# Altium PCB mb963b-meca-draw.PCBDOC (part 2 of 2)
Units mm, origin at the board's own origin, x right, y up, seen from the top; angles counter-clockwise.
Board outline 55.97 x 112.25 mm, 2 copper layers (Top, Bottom), stack 0.323 mm thick; 137 components, 131 nets, 523 pads, 261 vias.
Unrouted connection lines stored in the file: 17.
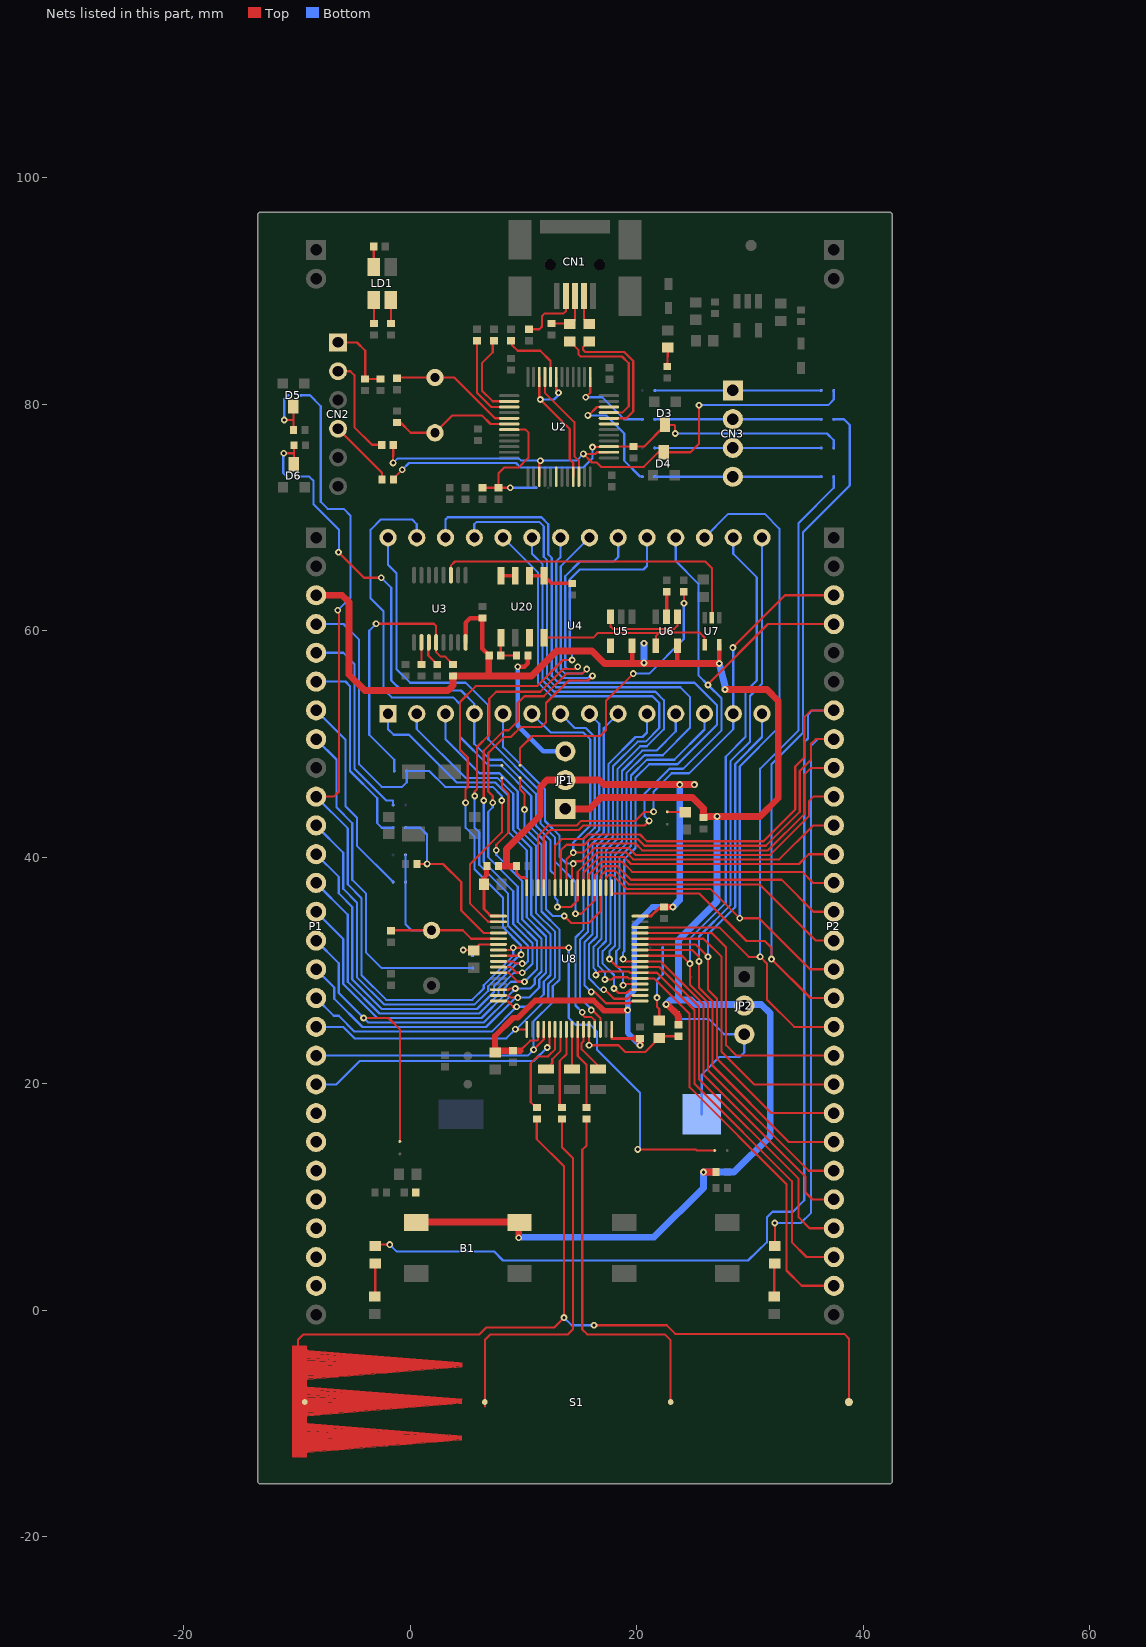
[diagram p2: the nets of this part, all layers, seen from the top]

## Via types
v1: diameter 0.6, hole 0.3, Top to Bottom, 261 vias

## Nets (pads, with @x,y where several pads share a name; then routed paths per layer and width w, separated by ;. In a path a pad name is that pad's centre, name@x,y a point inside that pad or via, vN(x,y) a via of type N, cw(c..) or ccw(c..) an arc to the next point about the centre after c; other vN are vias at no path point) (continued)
NETC25_1: C19.1 R29.2 U8.1 | length 5.4
  Top w0.254: C19.1@6.538,37.6 6.528,37.59 6.528,35.409 7.009,34.928 7.009,34.909 7.119,34.8 U8.1@7.8,34.8
  Top w0.4: C19.1@6.538,37.6 6.538,38.2 6.746,38.408 6.746,39.154 R29.2@6.792,39.2
NETCN1_1: CN2.1 R11.1 R101.2 | length 6.6
  Top w0.191: CN2.1@-6.362,85.439 -4.694,85.439 -3.965,84.71 R101.2@-3.965,82.211 -2.603,82.211 R11.1@-2.6,82.208
NETCN1_2: CN2.2 R13.1 | length 9.2
  Top w0.191: CN2.2@-6.362,82.899 -5.276,82.899 -4.921,82.544 -4.921,77.953 -3.366,76.398 -3.364,76.4 R13.1@-2.508,76.4
NETCN1_4: CN2.4 R14.1 | length 6.1
  Top w0.191: CN2.4@-6.362,77.819 -2.482,73.939 R14.1@-2.482,73.329
NETCN2_1: CN3.1 SB6.1 SB7.2 | length 14.7
  Bottom w0.191: SB6.1@21.6,81.2 CN3.1@28.5,81.2 SB7.2@36.3,81.2
NETCN2_2: CN3.2 SB8.1 SB9.2 | length 14.7
  Bottom w0.191: SB8.1@21.6,78.66 CN3.2@28.5,78.66 SB9.2@36.3,78.66
NETCN2_3: CN3.3 SB10.1 SB11.2 | length 14.7
  Bottom w0.191: SB10.1@21.6,76.12 CN3.3@28.5,76.12 SB11.2@36.3,76.12
NETCN2_4: CN3.4 SB12.1 SB13.2 | length 14.7
  Bottom w0.191: SB12.1@21.6,73.58 CN3.4@28.5,73.58 SB13.2@36.3,73.58
NETCN3_2: CN1.2 R10.1 | length 2.7
  Top w0.191: CN1.2@15.357,89.55 15.357,87.5 15.795,87.062 R10.1@15.8,87.062
NETCN3_3: CN1.3 R8.1 R9.1 | length 4.4
  Top w0.191: R8.1@12.5,87.108 14.085,87.108 R9.1@14.12,87.073 ; R9.1@14.1,87.062 R9.1@14.12,87.073 ; CN1.3@14.557,89.55 14.557,87.319 R9.1@14.12,87.073
NETCN3_4: CN1.4 R7.1 | length 5.8
  Top w0.191: R7.1@10.5,86.608 11.4,86.608 11.643,86.852 11.643,87.752 11.892,88 13.557,88 13.757,88.2 CN1.4@13.757,89.55
NETCR1_1: CR1.1 JP2.3 SB22.1 | length 16.6
  Bottom w0.191: SB22.1@23.7,26.3 23.7,25.7 24.129,25.7 26.4,25.7 27.74,24.36 JP2.3@29.5,24.36 29.5,22.75 29.1,22.35 27.3,22.35 25.75,20.8 CR1.1@25.75,17.3
NETJP1_3: JP1.3 R22.1 U5.4 U20.7 U20.8 | length 13.3
  Top w0.3: U20.8@8.012,64.84 U20.7@9.282,64.84
  Top w0.4: v1(9.5,56.8) 10.1,56.8 10.4,57.1 10.4,57.808 R22.1@10.408,57.8
  Bottom w0.4: v1(9.5,56.8) 9.5,51.6 11.76,49.34 JP1.3@13.7,49.34
NETLD1_2: LD1.2 R3.2 | length 2.1
  Top w0.191: R3.2@-1.7,87.108 LD1.2@-1.7,89.2
NETLD1_3: LD1.3 R2.2 | length 2.1
  Top w0.191: R2.2@-3.2,87.108 LD1.3@-3.2,89.2
NETLD1_4: LD1.4 R1.1 | length 1.8
  Top w0.191: R1.1@-3.208,93.9 -3.208,92.108 LD1.4@-3.2,92.1
NETLD2_1: LD2.1 R12.1 | length 1.7
  Top w0.191: R12.1@22.7,83.308 LD2.1@22.759,84.979
NETLD3_1: LD3.1 R39.1 | length 3
  Top w0.191: LD3.1@-3.139,1.203 -3.135,1.401 -3.08,1.456 R39.1@-3.08,4.138
NETLD4_1: LD4.1 R40.1 | length 3
  Top w0.191: LD4.1@32.141,1.203 32.141,4.079 R40.1@32.2,4.138
NETR1_1: R18.1 U6.2 | length 2.3
  Top w0.3: U6.2@22.645,61.213 22.659,61.199 R18.1@22.659,63.43
NETR2_2: R19.2 SB2.1 | length 25.7
  Top w0.191: SB2.1@9.7,48.1 9.7,49.6 10.8,50.7 16.8,50.7 17.3,51.2 17.3,53.8 v1(19.7,56.2) ; R19.2@24.159,63.43 24.178,63.411 v1(24.178,62.421)
  Bottom w0.191: v1(19.7,56.2) 21.111,56.2 24.163,59.252 24.163,62.421 v1(24.178,62.421)
NETR3_1: R21.1 R22.2 U20.1 | length 3
  Top w0.191: U20.1@8.012,59.379 8.008,59.375 R21.1@8.008,57.8 R22.2@9.392,57.8
NETR5_1: R20.1 SB1.1 U20.5 U20.6 | length 4
  Top w0.3: U20.6@10.552,64.84 U20.5@11.822,64.84
  Top w0.33: U20.5@11.822,64.84 12.49,64.172 14.312,64.172 R20.1@14.316,64.168
NETR6_2: R25.2 SB14.1 U3.12 | length 23.8
  Top w0.191: v1(-3,60.6) 2.1,60.6 2.3,60.4 U3.12@2.3,58.956 2.3,58.1 2.7,57.7 3.108,57.7 R25.2@3.8,57.008
  Bottom w0.191: v1(-3,60.6) -3.6,60 -3.6,50.8 -1.4,48.6 SB14.1@-1.4,47.6
NETR7_1: R23.1 U3.10 | length 1.9
  Top w0.191: R23.1@1,57.008 U3.10@1,58.956
NETR8_1: R24.1 U3.11 | length 2.3
  Top w0.191: U3.11@1.65,58.956 1.608,58.914 1.608,57.8 R24.1@2.4,57.008
NETR9_2: R6.2 U2.44 | length 5.8
  Top w0.191: R6.2@8.9,85.592 9.001,85.491 9.001,85.2 9.5,84.701 11.5,84.701 12.401,83.8 U2.44@12.401,82.389
NETR10_2: R5.2 U2.2 | length 7.7
  Top w0.191: R5.2@7.4,85.592 7.3,85.592 7.3,84.561 6.339,83.6 6.339,81.2 7.3,80.239 U2.2@8.751,80.239
NETR11_2: R4.2 U2.3 | length 8
  Top w0.191: R4.2@5.9,85.592 5.9,81 7.161,79.739 U2.3@8.751,79.739
NETR26_2: R28.2 SB16.1 U8.4 | length 15.9
  Top w0.191: R28.2@0.608,39.4 v1(1.5,39.4) 2.91,39.4 4.51,37.8 4.51,37.6 4.51,35.29 6.5,33.3 U8.4@7.8,33.3
  Bottom w0.191: SB16.1@-0.4,42.6 0.9,42.6 1.5,42 v1(1.5,39.4)
NETR30_1: R26.1 SB3.2 | length 1.6
  Top w0.191: SB3.2@22.7,44 24.3,44 R26.1@24.3,43.962
NETR34_2: R31.2 SB19.2 | length 6.7
  Top w0.191: v1(21.8,27.6) 21.8,26.8 22,26.6 R31.2@22,25.562
  Bottom w0.191: v1(21.8,27.6) 21.8,29.155 22.3,29.655 SB19.2@22.3,32
NETT1_3: U6.4 U7.4 U20.4 | length 16.4
  Top w0.191: U20.4@11.822,59.379 16.176,59.379 16.579,59.782 21.972,59.782 ; U6.4@21.695,58.673 21.695,59.505 21.972,59.782 ; U7.4@25.995,58.743 25.995,59.388 25.566,59.817 22.007,59.817 21.972,59.782
NETU1_3: U5.3 U6.1 | length 7.7
  Top w0.191: U5.3@17.695,61.213 17.691,61.209 17.691,60.363 17.904,60.15 23.327,60.15 23.595,60.418 U6.1@23.595,61.213
NETU3_2: U3.3 U7.2 | length 28.7
  Top w0.191: U3.3@3.6,64.9 3.6,65.738 3.962,66.1 3.975,66.113 26.041,66.113 26.645,65.509 26.645,64.5 U7.2@26.645,61.143
NRST: P1.10 SB5.1 SB100.2 U8.7 | length 109.5
  Top w0.191: P1.10@-8.3,45.34 -6.73,45.34 -6.275,45.795 -6.275,61.799 v1(-6.38,61.799) ; U8.7@7.8,31.8 8.9,31.8 v1(9.1,32) v1(14,32) ; v1(20.1,14.2) 25.21,14.2 25.31,14.1 SB5.1@26.9,14.1
  Bottom w0.191: SB100.2@-9.676,80.773 -8.839,80.773 -7.884,79.818 -7.884,71.365 -7.262,70.743 -5.863,70.743 -5.268,70.148 -5.268,62.911 v1(-6.38,61.799) ; P1.10@-8.3,45.34 -5.5,42.54 -5.5,37.6 -4.3,36.4 -4.3,29.6 -2.1,27.4 5.5,27.4 6.5,28.4 6.5,28.7 9.1,31.3 v1(9.1,32) ; v1(14,32) 14,25.8 14.6,25.2 15.9,25.2 16.5,24.6 16.5,23 20.3,19.2 20.3,14.4 v1(20.1,14.2)
OSC_IN: C8.2 U2.5 X1.2 | length 11.5
  Top w0.191: C8.2@-1.15,82.278 -1.15,82.34 X1.2@2.2,82.34 3.899,82.34 7.5,78.739 U2.5@8.751,78.739
OSC_OUT: C9.2 U2.6 X1.1 | length 11.2
  Top w0.191: C9.2@-1.15,78.362 -0.84,78.362 0.062,77.46 X1.1@2.2,77.46 3.74,79 6.339,79 7.1,78.239 U2.6@8.751,78.239
PA0: P1.15 SB1.2 SB4.1 U8.14 | length 61.2
  Top w0.191: v1(-4.1,25.8) -1.9,25.8 -0.9,24.8 SB4.1@-0.9,14.9 ; v1(7.6,40.6) 7.6,41.1 8.7,42.2 8.7,45.6 8.1,46.2 SB1.2@8.1,47 ; U8.14@7.8,28.3 8.684,28.3 8.784,28.4 v1(9.3,28.4)
  Bottom w0.191: P1.15@-8.3,32.64 -6.3,30.64 -6.3,28 v1(-4.1,25.8) -3.7,25.4 6.5,25.4 8.7,27.6 8.7,27.8 v1(9.3,28.4) 10.6,28.4 11,28.8 11,29.3 11.6,29.9 11.6,32.8 9.9,34.5 9.9,37.9 7.6,40.2 v1(7.6,40.6)
PA1: P1.16 U4.1 U8.15 | length 58.6
  Top w0.191: U8.15@7.8,27.8 8.7,27.8 8.9,27.6 v1(9.5,27.6)
  Bottom w0.191: P1.16@-8.3,30.1 -6.7,28.5 -6.7,27.5 -4.2,25 6.7,25 9.3,27.6 v1(9.5,27.6) 10.5,27.6 11.4,28.5 11.4,29.2 12,29.8 12,33 10.3,34.7 10.3,40.6 8.7,42.2 8.7,45.4 7.5,46.6 4.1,46.6 -0.1,50.8 -1.45,50.8 -1.95,51.3 U4.1@-1.95,52.66
PA2: P1.17 U4.2 U8.16 | length 56
  Top w0.191: U8.16@7.8,27.3 8.6,27.3 9.1,26.8 v1(9.4,26.8)
  Bottom w0.191: P1.17@-8.3,27.56 -6.74,26 -6.3,26 -4.9,24.6 7.2,24.6 v1(9.4,26.8) 10.7,26.8 11.8,27.9 11.8,29 12.4,29.6 12.4,33.2 10.7,34.9 10.7,40.8 9.1,42.4 9.1,45.6 7.7,47 4.89,47 0.59,51.3 U4.2@0.59,52.66
PA3: P1.18 U4.3 U8.17 | length 53.8
  Top w0.191: v1(9.3,24.8) U8.17@10.3,24.8
  Bottom w0.191: P1.18@-8.3,25.02 -5.9,25.02 -5.9,25 -4.9,24 8.5,24 v1(9.3,24.8) 9.381,24.8 12.2,27.619 12.2,28.8 12.8,29.4 12.8,33.4 11.1,35.1 11.1,41 9.5,42.6 9.5,45.8 7.9,47.4 6.13,47.4 3.13,50.4 U4.3@3.13,52.66
PA4: P1.19 SB2.2 U8.20 | length 48
  Top w0.191: SB2.2@9.7,47 9.7,46 10.1,45.6 v1(10.1,44.2) ; v1(10.9,23) 11.8,23.9 U8.20@11.8,24.8
  Bottom w0.191: P1.19@-8.3,22.48 10.38,22.48 v1(10.9,23) 10.9,25.5 12.6,27.2 12.6,28.6 13.2,29.2 13.2,33.6 11.6,35.2 11.6,41.1 10.1,42.6 v1(10.1,44.2)
PA5: P1.20 U8.21 | length 23.4
  Top w0.191: v1(12.1,23.2) 12.3,23.4 U8.21@12.3,24.8
  Bottom w0.191: P1.20@-8.3,19.94 -6.5,19.94 -4.44,22 10.9,22 v1(12.1,23.2)
PA6: R33.1 U8.22 | length 8.6
  Top w0.191: R33.1@11.185,17.908 11.178,17.915 11.097,17.915 10.657,18.355 10.657,21.796 11.261,22.4 12.17,22.4 12.221,22.451 12.221,22.465 12.8,23.044 U8.22@12.8,24.8
PA7: C27.2 U8.23 | length 4
  Top w0.191: C27.2@12,21.3 12.554,21.854 12.554,22.167 13.289,22.902 13.289,24.789 U8.23@13.3,24.8
PA8: P2.23 U4.16 U8.41 | length 70.5
  Top w0.191: U8.41@20.3,31.3 24,31.3 v1(24.7,30.6) 24.7,28.756 26.3,27.156 26.3,21.2 35.18,12.32 P2.23@37.42,12.32
  Bottom w0.191: v1(24.7,30.6) 24.7,32.8 27.866,35.966 27.866,48.866 29.6,50.6 29.6,54.6 30.6,55.6 30.6,64.7 28.53,66.77 U4.16@28.53,68.2
PA9: P2.22 U4.15 U8.42 | length 68.8
  Top w0.191: U8.42@20.3,31.8 24.9,31.8 25.5,31.2 v1(25.5,30.8) 25.5,28.483 26.7,27.283 26.7,21.6 33.44,14.86 P2.22@37.42,14.86
  Bottom w0.191: v1(25.5,30.8) 25.5,33 28.3,35.8 28.3,48.5 30,50.2 30,54.23 31.07,55.3 U4.15@31.07,68.2
PA10: P2.21 U4.14 U8.43 | length 51.5
  Top w0.191: U8.43@20.3,32.3 25.2,32.3 v1(26.3,31.2) 26.3,28.3 27.1,27.5 27.1,22.2 31.9,17.4 P2.21@37.42,17.4
  Bottom w0.191: v1(26.3,31.2) 26.3,33.2 28.7,35.6 28.7,48.23 31.07,50.6 U4.14@31.07,52.66
PA11: P2.20 U8.44 | length 27.4
  Top w0.191: U8.44@20.3,32.8 25.9,32.8 27.5,31.2 27.5,22.8 30.36,19.94 P2.20@37.42,19.94
PA12: P2.19 U8.45 | length 26.7
  Top w0.191: U8.45@20.3,33.3 26.625,33.3 27.9,32.025 27.9,23.4 28.82,22.48 P2.19@37.42,22.48
PA13: P2.18 SB13.1 U8.46 | length 67.7
  Top w0.191: U8.46@20.3,33.8 27.3,33.8 29.9,31.2 v1(30.9,31.2) 31.5,30.6 31.5,29.8 31.5,27.42 33.9,25.02 P2.18@37.42,25.02
  Bottom w0.191: v1(30.9,31.2) 30.9,47.8 34.3,51.2 34.3,69.5 37.4,72.6 SB13.1@37.4,73.58
PA14: P2.17 SB9.1 U8.49 | length 76.2
  Top w0.191: U8.49@17.8,37.3 17.8,36.8 25.5,36.8 29.7,32.6 31.3,32.6 31.9,32 v1(31.9,31) 35.34,27.56 P2.17@37.42,27.56
  Bottom w0.191: v1(31.9,31) 31.9,48.2 34.7,51 34.7,68.7 38.807,72.807 38.807,78.153 38.3,78.66 SB9.1@37.4,78.66
PA15: P2.16 U4.17 U8.50 | length 68.7
  Top w0.191: U8.50@17.3,37.3 17.3,38.2 17.5,38.4 17.9,38.4 19.1,37.2 26.5,37.2 v1(29.1,34.6) 30.8,34.6 35.3,30.1 P2.16@37.42,30.1
  Bottom w0.191: U4.17@25.99,68.2 28.09,70.3 31.3,70.3 32.6,69 32.6,51.5 29.1,48 29.1,34.8 29.3,34.6 v1(29.1,34.6)
PB0: R35.1 U8.26 | length 7.2
  Top w0.191: U8.26@14.8,24.8 14.8,22.438 15.569,21.669 R35.1@15.569,17.908
PB1: C29.2 U8.27 | length 4.2
  Top w0.191: U8.27@15.3,24.8 15.3,23.746 15.145,23.591 15.145,23.03 16.645,21.53 16.6,21.485 C29.2@16.6,21.3
PB2: P1.21 R31.1 R32.2 U8.28 | length 10.1
  Top w0.191: U8.28@15.8,24.8 v1(15.8,23.4) 18.4,23.4 19,22.8 20.762,22.8 R31.1@22,24.038 22.154,24.192 R32.2@23.7,24.192
PB3: P2.11 SB101.1 U4.4 U8.55 | length 82
  Top w0.191: v1(-6.316,66.92) -4.065,64.669 v1(-2.55,64.669) ; v1(13,35.6) 14.2,35.6 14.8,36.2 U8.55@14.8,37.3 14.8,38.7 16.5,40.4 19.1,40.4 19.7,39.8 32.6,39.8 35.6,42.8 P2.11@37.42,42.8
  Bottom w0.191: SB101.1@-9.795,73.594 -8.901,73.594 -8.522,73.215 -8.522,71.154 -6.271,68.903 -6.271,66.92 v1(-6.316,66.92) ; v1(-2.55,64.669) -1.658,63.777 -1.658,55.598 -0.766,54.706 4.493,54.706 5.651,53.548 5.67,53.529 U4.4@5.67,52.66 5.67,52.478 5.67,50 7.07,48.6 8.1,48.6 11.1,45.6 11.1,42.8 12.4,41.5 12.4,38.8 12.8,38.4 12.8,36.4 13,36.2 v1(13,35.6)
PB4: P2.10 U4.5 U8.56 | length 45.1
  Top w0.191: U8.56@14.3,37.3 14.3,39.333 v1(14.4,39.433) 14.6,39.633 15.133,39.633 16.3,40.8 19.3,40.8 19.9,40.2 31.8,40.2 35.2,43.6 35.2,44.94 35.6,45.34 P2.10@37.42,45.34
  Bottom w0.191: U4.5@8.21,52.66 8.21,49.695 11.905,46 11.905,43.195 13.2,41.9 13.2,40.033 13.8,39.433 v1(14.4,39.433)
PB5: P2.9 U4.6 U8.57 | length 48.7
  Top w0.191: U8.57@13.8,37.3 13.8,39.8 v1(14.4,40.4) 15.3,40.4 16.1,41.2 19.9,41.2 20.5,40.6 31.6,40.6 34.8,43.8 34.8,47.28 35.4,47.88 P2.9@37.42,47.88
  Bottom w0.191: U4.6@10.75,52.66 12.41,51 15.3,51 15.9,50.4 15.9,42.8 14.399,41.299 14.4,41.297 v1(14.4,40.4)
PB6: P2.8 R40.2 U8.58 | length 84
  Top w0.191: U8.58@13.3,37.3 13.3,40.6 13.8,41.1 15.4,41.1 15.9,41.6 20.1,41.6 20.7,41 31.4,41 34.4,44 34.4,47.6 35.39,48.59 35.39,50.01 35.8,50.42 P2.8@37.42,50.42 ; R40.2@32.2,5.662 v1(32.2,7.7)
  Bottom w0.191: v1(32.2,7.7) 34.5,7.7 35.4,8.6 35.4,49.82 36,50.42 P2.8@37.42,50.42
PB7: P2.7 R39.2 U8.59 | length 125.6
  Top w0.191: R39.2@-3.08,5.662 -2.9,5.662 -2.838,5.8 v1(-1.8,5.8) ; U8.59@12.8,37.3 12.8,41 13.4,41.6 15.3,41.6 15.7,42 20.3,42 20.9,41.4 31.2,41.4 34,44.2 34,48 34.8,48.8 34.8,52.36 35.4,52.96 P2.7@37.42,52.96
  Bottom w0.191: v1(-1.8,5.8) -1.213,5.213 0.6,5.2 7.4,5.2 8.2,4.4 29.826,4.4 31.5,6 31.5,8.2 32,8.7 33.8,8.7 34.8,9.7 34.8,50.157 35.12,50.477 35.12,52.58 35.5,52.96 P2.7@37.42,52.96
PB8: P2.4 U4.18 U8.61 | length 58.3
  Top w0.191: U8.61@11.8,37.3 11.8,41.8 12.4,42.4 14.9,42.4 15.3,42.8 20.7,42.8 v1(21.1,43.2) ; v1(26.3,55.2) 26.2,55.18 26.22,55.2 31.6,60.58 P2.4@37.42,60.58
  Bottom w0.191: v1(21.1,43.2) 20.7,43.6 20.7,45.6 22.9,47.8 24.1,47.8 27.5,51.2 27.5,54 v1(26.3,55.2) 25.447,56.053 25.447,64.147 23.45,66.144 U4.18@23.45,68.2
PB9: P2.3 U4.13 U8.62 | length 44.8
  Top w0.191: U8.62@11.3,37.3 11.3,41.9 12.2,42.8 14.7,42.8 15.1,43.2 19.9,43.2 20.7,44 v1(21.5,44) ; v1(28.5,58.5) 28.5,58.52 33.1,63.12 P2.3@37.42,63.12
  Bottom w0.191: v1(21.5,44) 21.5,45.8 23.1,47.4 24.63,47.4 28.53,51.3 U4.13@28.53,52.66 28.53,58.4 28.5,58.43 v1(28.5,58.5)
PB10: P1.22 U4.7 U8.29 | length 31.4
  Top w0.191: v1(15.2,26.3) 15.2,26.1 15.4,25.9 16,25.9 16.3,25.6 U8.29@16.3,24.8
  Bottom w0.191: U4.7@13.29,52.66 14.55,51.4 15.5,51.4 16.3,50.6 16.3,42.6 15.3,41.6 15.3,33.6 14.6,32.9 14.6,26.9 v1(15.2,26.3)
PB11: P1.23 U4.8 U8.30 | length 29.9
  Top w0.191: v1(16,26.5) 16,26.6 16.8,25.8 U8.30@16.8,24.8
  Bottom w0.191: U4.8@15.83,52.66 16.7,51.79 16.7,42.4 15.7,41.4 15.7,33.4 15,32.7 15,27.6 16,26.6 v1(16,26.5)
PB12: P1.24 U4.9 U8.33 | length 30.8
  Top w0.191: v1(16,28.1) 16.3,28.1 17.3,27.1 19.4,27.1 19.6,27.3 U8.33@20.3,27.3
  Bottom w0.191: v1(16,28.1) 15.4,28.7 15.4,32.5 16.1,33.2 16.1,41.2 17.1,42.2 17.1,51.39 U4.9@18.37,52.66
PB13: P1.25 U4.10 U8.34 | length 31.2
  Top w0.191: v1(17.1,28.3) 17.204,28.3 18.004,27.5 19.2,27.5 19.5,27.8 U8.34@20.3,27.8
  Bottom w0.191: v1(17.1,28.3) 16.8,28.3 15.8,29.3 15.8,32.3 16.5,33 16.5,41 17.5,42 17.5,48.2 19.9,50.6 20.51,50.6 20.91,51 U4.10@20.91,52.66
PB14: P1.26 U4.11 U8.35 | length 30.7
  Top w0.191: v1(18,28.4) 18.4,28 19.1,28 19.4,28.3 U8.35@20.3,28.3
  Bottom w0.191: v1(18,28.4) 18,29.6 17,30.6 17,31.2 17,31.7 17.7,32.4 17.7,40.4 18.7,41.4 18.7,47.6 20.5,49.4 21.75,49.4 23.45,51.1 U4.11@23.45,52.66
PB15: P1.27 U4.12 U8.36 | length 30.4
  Top w0.191: v1(18.8,28.7) 18.861,28.7 18.9,28.739 18.991,28.739 19.052,28.8 U8.36@20.3,28.8
  Bottom w0.191: v1(18.8,28.7) 18.8,29.8 18.2,30.4 18.2,31.7 18.5,32 18.5,40 19.5,41 19.5,47.2 20.9,48.6 23.323,48.6 25.99,51.267 U4.12@25.99,52.66
PC0: P1.11 U4.19 U8.8 | length 87.6
  Top w0.191: v1(4.9,44.8) 4.9,45.991 5.084,46.175 5.084,48.792 4.4,49.476 4.4,53.7 5.8,55.1 11.2,55.1 13.5,57.4 v1(14.3,57.4) ; U8.8@7.8,31.3 9.471,31.3 9.542,31.371 9.691,31.371 9.693,31.373 v1(9.8,31.4)
  Bottom w0.191: P1.11@-8.3,42.8 -5.9,40.4 -5.9,37.2 -4.7,36 -4.7,29.4 -2.3,27 5.7,27 6.9,28.2 6.9,28.6 9.7,31.4 v1(9.8,31.4) 9.8,31.8 9.796,31.804 9.796,32.204 8.2,33.8 8.2,36.412 5.7,38.912 5.7,41.8 4.9,42.6 v1(4.9,44.8) ; v1(14.3,57.4) 14.3,58.1 14.1,58.3 14.1,64.513 14.987,65.4 20.61,65.4 20.91,65.7 U4.19@20.91,68.2
PC1: P1.12 U4.20 U8.9 | length 84.2
  Top w0.191: v1(5.7,45.4) 5.7,45.8 5.9,46 5.9,49.725 6.984,50.809 6.984,53.984 7.6,54.6 11.5,54.6 13.5,56.6 14.6,56.6 v1(14.8,56.8) ; U8.9@7.8,30.8 9.1,30.8 9.3,30.6 v1(9.9,30.6)
  Bottom w0.191: P1.12@-8.3,40.26 -6.3,38.26 -6.3,36.8 -5.1,35.6 -5.1,29.2 -2.5,26.6 5.9,26.6 7.4,28.1 7.4,28.6 9.4,30.6 v1(9.9,30.6) 10.2,30.6 10.4,30.8 10.4,32.2 8.63,33.97 8.63,36.8 6.1,39.33 6.1,42.2 5.7,42.6 v1(5.7,45.4) ; v1(14.8,56.8) 14.6,56.6 13.9,56.6 13.7,56.8 13.7,64.8 15,66.1 17.97,66.1 18.37,66.5 U4.20@18.37,68.2
PC2: P1.13 U4.21 U8.10 | length 80.7
  Top w0.191: v1(6.5,45) 6.5,49.4 8.3,51.2 8.7,51.2 9.5,52 9.5,53.6 10.1,54.2 11.8,54.2 13.8,56.2 15.2,56.2 v1(15.6,56.6) ; U8.10@7.8,30.3 8.9,30.3 9.4,29.8 v1(9.9,29.8)
  Bottom w0.191: P1.13@-8.3,37.72 -5.5,34.92 -5.5,29 -2.7,26.2 6.1,26.2 7.8,27.9 7.8,28.44 9.16,29.8 v1(9.9,29.8) 10,29.8 10.8,30.6 10.8,32.4 9.1,34.1 9.1,37 6.5,39.6 v1(6.5,45) ; v1(15.6,56.6) 15.2,56.2 13.7,56.2 13.3,56.6 13.3,65.67 U4.21@15.83,68.2
PC3: P1.14 U4.22 U8.11 | length 80.2
  Top w0.191: v1(7.3,44.8) 7.3,45.4 6.9,45.8 6.9,49.2 8.3,50.6 8.9,50.6 9.8,51.5 11.6,51.5 12,51.9 12,53.6 14,55.6 15.7,55.6 v1(16.1,56) ; U8.11@7.8,29.8 8.7,29.8 9.5,29 v1(10.1,29)
  Bottom w0.191: P1.14@-8.3,35.18 -5.9,32.78 -5.9,28.8 -2.9,25.8 6.3,25.8 8.3,27.8 8.3,28.4 8.9,29 v1(10.1,29) 11.2,30.1 11.2,32.6 9.5,34.3 9.5,37.4 6.9,40 6.9,44 7.3,44.4 v1(7.3,44.8) ; U4.22@13.29,68.2 13.29,66.5 12.9,66.11 12.9,56.4 13.5,55.8 15.7,55.8 15.9,56 v1(16.1,56)
PC4: R34.1 U8.24 | length 7.3
  Top w0.191: R34.1@13.4,17.908 13.4,17.921 13.477,17.998 13.216,18.259 13.216,22.016 13.8,22.6 U8.24@13.8,24.8
PC5: C28.2 U8.25 | length 3.5
  Top w0.191: C28.2@14.3,21.3 U8.25@14.3,24.8
PC6: P2.27 U4.23 U8.37 | length 91.9
  Top w0.191: v1(17.2,29.2) 17.8,29.2 18,29.4 19.2,29.4 19.3,29.3 U8.37@20.3,29.3 21.526,29.3 24.675,26.151 24.675,19.692 33.23,11.137 33.23,3.506 34.578,2.158 34.58,2.16 P2.27@37.42,2.16
  Bottom w0.191: U4.23@10.75,68.2 10.75,66.8 11.7,65.85 11.7,55.6 12.7,54.6 21.661,54.6 22.4,53.861 22.4,51.286 20.9,49.786 20.314,49.786 18.3,47.771 18.3,41.6 17.3,40.6 17.3,32.6 16.6,31.9 16.6,30.4 17.2,29.8 v1(17.2,29.2)
PC7: P2.26 U4.24 U8.38 | length 91
  Top w0.191: v1(16.4,29.6) 16.7,29.9 19.3,29.9 19.4,29.8 U8.38@20.3,29.8 21.8,29.8 25.1,26.5 25.1,20 33.7,11.4 33.7,6 35,4.7 P2.26@37.42,4.7
  Bottom w0.191: U4.24@8.21,68.2 11.3,65.11 11.3,55.4 12.5,54.2 21.4,54.2 22,53.6 22,51.4 20.8,50.2 20.1,50.2 17.9,48 17.9,41.8 16.9,40.8 16.9,32.8 16.2,32.1 16.2,30.2 16.4,30 v1(16.4,29.6)
PC8: P2.25 U4.25 U8.39 | length 96.8
  Top w0.191: v1(17.6,31) 18.3,30.3 U8.39@20.3,30.3 22,30.3 25.5,26.8 25.5,20.4 34.3,11.6 34.3,8.2 35.26,7.24 P2.25@37.42,7.24
  Bottom w0.191: U4.25@5.67,68.2 5.67,69.4 5.87,69.6 11.4,69.6 11.8,69.2 11.8,66.504 12.1,66.204 12.1,55.8 12.9,55 23.846,55 24.7,54.146 24.7,51.4 22.3,49 20.694,49 19.094,47.4 19.094,41.194 18.1,40.2 18.1,32.2 17.6,31.7 v1(17.6,31)
PC9: P2.24 U4.26 U8.40 | length 99.4
  Top w0.191: v1(18.8,31) 19,30.8 U8.40@20.3,30.8 22.1,30.8 25.9,27 25.9,20.8 34.9,11.8 34.9,10.4 35.52,9.78 P2.24@37.42,9.78
  Bottom w0.191: U4.26@3.13,68.2 3.13,69.8 3.33,70 11.6,70 12.2,69.4 12.2,66.718 12.5,66.418 12.5,56 13.1,55.4 25.1,55.4 27.1,53.4 27.1,51.7 23.6,48.2 21.1,48.2 19.9,47 19.9,40.8 18.9,39.8 18.9,31.69 18.8,31.59 v1(18.8,31)
PC10: P2.15 U4.27 U8.51 | length 81.7
  Top w0.191: v1(13.6,34.8) 14.2,34.2 15.8,34.2 16.8,35.2 U8.51@16.8,37.3 16.8,38.3 17.3,38.8 18.1,38.8 19.3,37.6 30.84,37.6 35.8,32.64 P2.15@37.42,32.64
  Bottom w0.191: U4.27@0.59,68.2 0.59,69.4 0.19,69.8 -2.591,69.8 -3.486,68.905 -3.486,68.873 -3.486,62.828 -3.476,62.828 -2.351,61.703 -2.351,54.84 -2.102,54.591 -2.102,54.584 -1.619,54.101 3.803,54.101 4.4,53.504 4.4,50.6 6.9,48.1 8,48.1 10.7,45.4 10.7,42.6 12,41.3 12,35.4 12.6,34.8 v1(13.6,34.8)
PC11: P2.14 U4.28 U8.52 | length 70.5
  Top w0.191: v1(14.6,35) 15.1,35 16.3,36.2 U8.52@16.3,37.3 16.3,38.4 17.1,39.2 18.3,39.2 19.5,38 32.8,38 35.6,35.2 35.6,35.18 P2.14@37.42,35.18
  Bottom w0.191: U4.28@-1.95,68.2 -1.95,65.8 -1.2,65.05 -1.2,56.6 0,55.4 4.9,55.4 6.9,53.4 6.9,50.4 11.5,45.8 11.5,43 12.8,41.7 12.8,39.6 14.6,37.8 v1(14.6,35)
PC12: P2.13 U8.53 | length 24.1
  Top w0.191: U8.53@15.8,37.3 15.8,38.5 16.9,39.6 18.7,39.6 19.6,38.7 34.62,38.7 35.6,37.72 P2.13@37.42,37.72
PC13: P1.4 SB14.2 U8.2 | length 44.7
  Top w0.191: U8.2@7.8,34.3 6.9,34.3 5.3,35.9 5.3,38.8 5.3,39.4 8.1,42.2 v1(8.1,45)
  Bottom w0.191: P1.4@-8.3,60.58 -5.88,60.58 -4.5,59.2 -4.5,48.2 -2.5,46.2 -0.7,46.2 -0.3,46.6 SB14.2@-0.3,47.6 1.7,47.6 3.1,46.2 7.3,46.2 8.1,45.4 v1(8.1,45)
PC14: P1.5 SB15.2 | length 18
  Bottom w0.191: P1.5@-8.3,58.04 -5.9,58.04 -4.9,57.04 -4.9,47.8 -2.1,45 -1.98,45 -1.5,45 SB15.2@-1.5,44.6
PC15: P1.6 SB16.2 | length 17.8
  Bottom w0.191: P1.6@-8.3,55.5 -5.7,55.5 -5.3,55.1 -5.3,47.6 -2.9,45.2 -2.9,43 -2.5,42.6 SB16.2@-1.5,42.6
PD2: P2.12 U8.54 | length 24.6
  Top w0.191: U8.54@15.3,37.3 15.3,38.6 16.7,40 18.9,40 19.5,39.4 34.33,39.4 35.19,40.26 P2.12@37.42,40.26
PH0: P1.7 SB18.2 | length 18
  Bottom w0.191: P1.7@-8.3,52.96 -5.7,50.36 -5.7,45.4 -5.7,44.5 -4.7,43.5 -4.7,41 SB18.2@-1.5,37.8
PH0-OSC_IN: C21.2 SB17.1 SB18.1 U8.5 X3.2 | length 18.5
  Top w0.191: C21.2@-1.7,33.508 -1.668,33.54 X3.2@1.9,33.54 4.66,33.54 5.4,32.8 U8.5@7.8,32.8
  Bottom w0.191: SB17.1@-0.4,40.2 SB18.1@-0.4,37.8 -0.4,34.065 0.125,33.54 X3.2@1.9,33.54
PH1: P1.8 SB20.2 | length 30.6
  Bottom w0.191: P1.8@-8.3,50.42 -6.5,48.62 -6.5,44.4 -5.1,43 -5.1,38 -3.9,36.8 -3.9,31.6 -2.5,30.2 SB20.2@5.5,30.2
PH1-OSC_OUT: R30.2 SB20.1 U8.6 | length 4.7
  Top w0.191: v1(4.7,31.8) 5.497,31.8 R30.2@5.6,31.903 ; R30.2@5.6,31.762 R30.2@5.6,31.903 ; U8.6@7.8,32.3 6.095,32.3 5.698,31.903 R30.2@5.6,31.903
  Bottom w0.191: v1(4.7,31.8) 5.143,31.8 5.5,31.8 SB20.1@5.5,31.3
SLD_1: R33.2 S1.1 S1.4 | length 80.5
  Top w0.191: S1.1@-9.3,-8.1 -9.512,-8.287 -9.725,-8.075 -9.898,-7.902 -9.898,-4.181 -9.898,-2.604 -9.435,-2.141 6.095,-2.141 6.72,-1.516 12.718,-1.516 v1(13.583,-0.651) 13.583,12.712 11.185,15.11 R33.2@11.185,16.892 ; v1(16.238,-1.33) 22.656,-1.33 23.41,-2.084 38.333,-2.084 38.735,-2.486 S1.4@38.735,-8.1
  Bottom w0.191: v1(13.583,-0.651) 14.262,-1.33 v1(16.238,-1.33)
SLD_2: R34.2 S1.2 | length 33.4
  Top w0.191: R34.2@13.4,16.892 13.409,16.883 13.409,14.377 14.392,13.394 14.392,-1.651 13.904,-2.139 7.088,-2.139 6.6,-2.627 S1.2@6.6,-8.1 ; S1.2@6.6,-8.1 6.6,-8.5 S1.2@6.6,-8.1
SLD_3: R35.2 S1.3 | length 32.4
  Top w0.191: R35.2@15.569,16.892 15.569,14.533 15.2,14.164 15.2,-1.7 15.625,-2.125 22.482,-2.125 23,-2.643 S1.3@23,-8.1
STM_JTCK: SB8.2 U2.37 | length 7.8
  Top w0.191: v1(15.5,80.6) 15.9,81 ; 15.901,81 U2.37@15.901,82.389
  Bottom w0.191: v1(15.5,80.6) 16.96,80.6 18.9,78.66 SB8.2@20.5,78.66
STM_JTMS: SB12.2 U2.34 | length 10.6
  Top w0.191: v1(15.7,79) 15.761,79 16.5,79.739 U2.34@17.551,79.739
  Bottom w0.191: v1(15.7,79) 17.3,79 18.9,77.4 18.9,75 20.3,73.6 20.476,73.6 20.48,73.6 SB12.2@20.5,73.58
STM_RST: C11.2 R17.1 SB102.2 U2.7 | length 13.2
  Top w0.191: R17.1@6.4,72.608 C11.2@7.8,72.608 ; U2.7@8.751,77.739 10.2,77.739 10.439,77.5 10.439,75.247 9.596,74.404 8.304,74.404 7.8,73.9 C11.2@7.8,72.608 ; v1(8.849,72.614) 7.806,72.614 C11.2@7.8,72.608
  Bottom w0.191: v1(8.849,72.614) SB102.2@11.103,72.614
SWIM: U2.22 U2.45 | length 10
  Top w0.191: U2.45@11.901,82.389 11.901,81.001 14.501,78.401 14.501,75.4 14.901,75 U2.22@14.901,73.589
SWIM_IN: U2.21 U2.43 U2.46 | length 13.5
  Top w0.191: U2.46@11.401,82.389 11.401,80.4 v1(11.5,80.4) 14.1,77.8 14.1,75.101 14.401,74.8 U2.21@14.401,73.589 ; U2.43@12.901,82.389 12.901,81.2 v1(13.1,81)
  Bottom w0.191: v1(11.5,80.4) 12.7,80.4 13.1,80.8 v1(13.1,81)
T_JTCK: D4.3 R13.2 SB7.1 U2.15 U2.26 | length 50.6
  Top w0.191: v1(-1.5,74.8) -1.5,75.392 -1.492,75.4 R13.2@-1.492,76.4 ; U2.15@11.401,73.589 11.401,75 v1(11.5,75) ; U2.26@17.551,75.739 16.5,75.739 16.361,75.6 v1(15.3,75.6) 16.065,74.835 16.491,74.835 16.883,74.443 20.631,74.443 20.631,74.452 21.92,75.741 D4.3@22.4,75.741 24.759,75.741 25.5,76.483 v1(25.5,79.9)
  Bottom w0.191: v1(-1.5,74.8) -1.1,75.2 9.6,75.2 9.8,75 v1(11.5,75) 14.7,75 v1(15.3,75.6) ; v1(25.5,79.9) 36.9,79.9 37.4,80.4 SB7.1@37.4,81.2
T_JTMS: D3.3 R14.2 R100.2 SB11.1 U2.27 | length 43.5
  Top w0.191: R14.2@-1.466,73.329 -1.492,73.408 v1(-0.7,74.2) ; v1(16.1,76.2) 17.551,76.2 U2.27@17.551,76.239 20.641,76.239 22.5,78.098 D3.3@22.5,78.159 23.3,78.159 23.4,78.059 v1(23.4,77.4)
  Bottom w0.191: v1(-0.7,74.2) -0.1,74.8 9.342,74.8 9.732,74.411 15.311,74.411 16.1,75.2 v1(16.1,76.2) ; v1(23.4,77.4) 36.8,77.4 37.4,76.8 SB11.1@37.4,76.12
T_NRST: D5.3 R102.1 SB100.1 U2.18 | length 5.2
  Top w0.191: v1(-11.114,78.592) -10.295,78.592 ; D5.3@-10.299,79.78 -10.295,79.776 -10.295,78.592 ; R102.1@-10.295,77.715 -10.295,78.592
  Bottom w0.191: v1(-11.114,78.592) -11.114,80.435 SB100.1@-10.776,80.773
T_SWO: D6.3 R103.2 SB101.2 U2.31 | length 4.8
  Top w0.191: v1(-11.152,75.649) -10.262,75.649 ; D6.3@-10.262,74.694 -10.262,75.649 ; R103.2@-10.256,76.364 -10.262,76.358 -10.262,75.649
  Bottom w0.191: v1(-11.152,75.649) -11.204,75.649 -11.204,73.903 SB101.2@-10.895,73.594
USB_DM: R10.2 U2.32 | length 12.7
  Top w0.191: R10.2@15.8,85.538 15.262,85 15.262,84.8 15.462,84.6 18.9,84.6 19.7,83.8 19.7,79.339 19.1,78.739 U2.32@17.551,78.739
USB_DP: R9.2 U2.33 | length 12
  Top w0.191: R9.2@14.1,85.538 14.854,84.784 14.854,84.4 15.054,84.2 18.7,84.2 19.3,83.6 19.3,79.8 18.739,79.239 U2.33@17.551,79.239
VDD: B1.1 B1.2 C14.2 C30.1 JP1.1 JP2.2 P1.3 R21.2 R25.1 R27.2 R32.1 R37.2 SB21.2 SB22.2 U3.16 U5.5 U6.5 U7.5 U20.3 | length 176.8
  Top w0.191: B1.1@1,7.749 1.051,7.8 B1.1@1.2,7.8
  Top w0.4: U3.16@4.9,58.956 4.9,60.711 5.291,61.102 C14.2@6.404,61.102 6.376,61.074 6.376,58.416 R21.2@6.992,57.8 ; 19.595,57.095 U5.5@19.595,58.673 ; 23.595,57.095 U6.5@23.595,58.673 ; v1(27.285,57.095) 27.285,58.733 U7.5@27.295,58.743
  Top w0.6: P1.3@-8.3,63.12 -6,63.12 -5.4,62.52 -5.4,56.1 -4,54.7 3.328,54.7 3.8,55.172 R25.1@3.8,55.992 6.946,55.992 ; B1.1@0.56,7.745 B1.1@1,7.749 ; B1.1@1.2,7.8 9.605,7.8 B1.2@9.66,7.745 9.6,7.685 v1(9.6,6.4) ; R21.2@7,57.8 R21.2@6.992,57.8 6.946,57.754 6.946,55.992 ; JP1.1@13.7,44.26 15.835,44.26 16.84,45.265 24.942,45.265 25.899,44.308 R27.2@25.9,43.601 ; v1(22.6,27) 22.7,27 23.65,26.05 23.65,25.95 23.7,25.9 R32.1@23.7,25.208 ; v1(25.9,12.2) R37.2@26.992,12.2 ; R27.2@25.9,43.508 R27.2@25.9,43.601 ; v1(27.285,57.095) 23.595,57.095 19.595,57.095 17.157,57.095 16.052,58.2 12.92,58.2 10.712,55.992 6.946,55.992 ; v1(27.8,54.8) 31.5,54.8 32.5,53.8 32.5,45.2 30.901,43.601 v1(27.1,43.6) R27.2@25.9,43.601
  Bottom w0.6: v1(9.6,6.4) 9.6,6.45 21.55,6.45 25.9,10.8 v1(25.9,12.2) 28.6,12.2 31.8,15.4 31.8,21.4 31.8,26.2 31,27 JP2.2@29.6,27 ; v1(20.65,57.145) v1(20.65,58.889) ; v1(22.6,27) 23,27.4 SB22.2@23.7,27.4 ; v1(27.1,43.6) 27.1,36.1 23.7,32.7 SB21.2@23.7,29.4 SB22.2@23.7,27.4 ; v1(27.285,57.095) 27.8,55.095 v1(27.8,54.8) ; JP2.2@29.5,26.9 JP2.2@29.6,27 ; SB22.2@23.7,27.4 24.8,27.4 25.2,27 JP2.2@29.6,27
VDD_MCU: C18.2 C20.2 C23.1 C25.2 JP1.2 L1.1 R29.1 U8.19 U8.32 U8.48 U8.64 | length 81.4
  Top w0.191: C18.2@9.31,39.228 9.312,39.225 C18.2@9.318,39.225 ; 9.7,22.908 9.768,22.976 9.776,22.976 10.6,23.8 11.2,23.8 11.3,23.9 U8.19@11.3,24.8 ; U8.48@20.3,34.8 20.895,34.8 U8.48@20.9,34.805 ; C20.2@22.5,35.608 C20.2@22.504,35.604
  Top w0.2: C18.2@9.318,39.225 C18.2@9.392,39.2
  Top w0.25: C18.2@9.392,39.2 9.392,38.6 9.792,38.2 10.1,38.2 10.3,38 U8.64@10.3,37.3 ; U8.32@17.8,24.8 17.8,23.992 19.9,23.992 ; U8.48@20.9,34.805 21.282,34.805 22.048,35.571 C20.2@22.4,35.571 ; C20.2@22.4,35.604 C20.2@22.4,35.571 ; C20.2@22.4,35.608 C20.2@22.4,35.571
  Top w0.4: C20.2@22.4,35.608 C20.2@22.5,35.608
  Top w0.5: L1.1@7.5,22.762 7.5,22.954 7.5,24.219 9.1,25.819 9.519,25.819 11.05,27.35 16.2,27.35 17.1,26.45 19.15,26.45 v1(19.2,26.5) ; C20.2@22.504,35.604 22.508,35.6 v1(23.2,35.6)
  Top w0.6: L1.1@7.546,22.954 7.592,22.908 C25.2@9.1,22.908 9.7,22.908 ; R29.1@7.808,39.2 8.5,39.2 ; C18.2@9.31,39.228 9.281,39.2 8.5,39.2 ; 19.9,23.992 C23.1@20.3,23.992 v1(20.3,23.4) ; v1(25.1,46.4) v1(23.8,46.4) 17.1,46.4 16.7,46.8 JP1.2@13.7,46.8 13.5,46.8 13.498,46.802 12.098,46.802 11.495,46.2 11.495,43.7 8.5,40.705 8.5,39.2
  Top w0.8: L1.1@7.5,22.762 7.546,22.808 L1.1@7.546,22.954
  Bottom w0.191: v1@23.1,35.6 v1(23.2,35.6)
  Bottom w0.5: v1(20.3,23.4) 19.2,24.5 v1(19.2,26.5) 19.2,27.7 19.8,28.3 19.8,34 21.4,35.6 v1@23.1,35.6
  Bottom w0.6: v1(23.2,35.6) 23.8,36.2 v1(23.8,46.4) v1(25.1,46.4)
pads on no net: CN1.6 CN1.7 M1.1 U2.4 U2.11 U2.12 U2.13 U2.14 U2.16 U2.17 U2.19 U2.28 U2.38 U2.39 U2.40 U2.41 U2.42 U3.1 U3.4 U3.5 U3.6 U3.7 U3.13 U3.14 U3.15 U7.1 X2.2 X2.3
copper on no net: | length 14.2
  Bottom w0.1: 1.14,0 ccw(c0,0) 1.14,0 ; 31.218,94 ccw(c30.1,94) 31.218,94

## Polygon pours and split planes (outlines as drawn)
GND on Bottom "Bottom-GND" (solid, remove dead copper, pour order 1000): -13.748,97.4 42.9,97.4 42.9,4.2 17.9,4.2 17.9,14 16.9,15 16.9,17.4 9.7,17.4 9.7,13.4 10.5,12.6 10.5,4.468 -13.7,4.468
GND on Bottom "Bottom-GND 1" (solid, remove dead copper, pour order 1001): 9.6,17.4 17,17.4 17,15.2 18,14.2 18,4.6 10.4,4.6 10.4,12.6 9.6,13.4
GND on Bottom "Bottom-GND 2" (solid, remove dead copper, pour order 1002): -13.7,5 42.7,5 42.7,-15.5 -13.7,-15.5
GND on Top "Top-GND" (solid, remove dead copper, pour order 1003): 42.6,-15.4 -13.6,-15.4 -13.6,0.6 42.6,0.6
GND on Top "Top-GND 1" (solid, remove dead copper, pour order 1004): -13.748,97.4 42.9,97.4 42.9,-0.2 -13.748,-0.2

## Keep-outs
Keep-Out Layer:
  lines w0.254: -13.3,-15.2 42.42,-15.2 42.42,96.8 -13.3,96.8 -13.3,-15.2

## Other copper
Top:
  pour cut-out: 17.8,-1.75 17.8,14.05 16.8,15 16.8,17.4 10,17.4 10,13.4 10.8,12.6 10.8,-1.75 17.8,-1.75
  pour cut-out: -11.904,-2.891 -11.879,-2.634 -11.793,-2.352 -11.654,-2.091 -11.466,-1.863 -11.238,-1.675 -10.978,-1.536 -10.695,-1.45 -10.401,-1.421 -10.255,-1.436 -10.254,-1.436 5.626,-1.436 6.136,-0.926 10.746,-0.926 10.741,-1.436 17.816,-1.436 17.816,-0.858 23.309,-0.858 23.865,-1.436 39.797,-1.431 39.822,-1.433 40.105,-1.519 40.365,-1.658 40.594,-1.846 40.781,-2.074 40.92,-2.335 41.006,-2.617 41.008,-2.637 41.003,-2.64 41.003,-12.801 41.019,-12.96 40.99,-13.254 40.904,-13.537 40.765,-13.797 40.577,-14.026 40.349,-14.213 40.088,-14.353 39.805,-14.438 39.511,-14.467 39.381,-14.454 39.38,-14.454 -10.579,-14.454 -10.719,-14.44 -11.001,-14.355 -11.262,-14.215 -11.49,-14.028 -11.678,-13.8 -11.817,-13.539 -11.903,-13.256 -11.905,-13.234 -11.9,-13.233 -11.9,-2.891
Bottom:
  pour cut-out: 13.431,0.281 16.222,0.281 16.37,0.266 16.675,0.174 16.956,0.024 17.202,-0.178 17.404,-0.425 17.554,-0.706 17.647,-1.01 17.678,-1.328 17.647,-1.645 17.554,-1.949 17.404,-2.23 17.202,-2.477 16.956,-2.679 16.675,-2.829 16.37,-2.921 16.222,-2.936 13.43,-2.94 13.163,-2.859 12.876,-2.706 12.625,-2.5 12.419,-2.248 12.265,-1.962 12.171,-1.651 12.139,-1.327 12.171,-1.004 12.265,-0.693 12.419,-0.407 12.625,-0.155 12.876,0.051 13.163,0.204 13.43,0.285 13.431,0.281

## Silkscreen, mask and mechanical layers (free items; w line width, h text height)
Silkscreen Top:
  drawing of 596 lines, arcs and shapes, not listed
  text "55.72mm" at 9.548,109.322 h1.52
  text "45.72mm" at 9.458,103.099 h1.52
  text "5mm" at 37.736,98.071 h1.52 r359.99
  text "5mm" at -12.983,97.562 h1.52 r0.01
  text "3.2mm" at -15.393,91.62 h1.52 r90
  text "3.2mm" at 56.362,91.62 h1.52 r90
  text "COM" at -0.1,89.9 h1
  text "2.54mm" at 51.155,88.013 h1.52 r90
  text "2.54mm" at -20.854,87.988 h1.52 r90
  text "SWD" at -12.645,84.927 h1.5
  text "1" at -4.788,84.786 h1
  text "PWR" at 21,84.2 h1 r90
  text "ST-LINK" at 25.4,74.6 h1.25 r90
  text "22.86mm" at 45.999,74.551 h1.52 r90
  text "22.86mm" at -16.993,74.525 h1.52 r90
  text "DISCOVERY" at 33,73 h1.25 r90
  text "www.st.com/stm32l-discovery" at -3.281,69.465 h1.75
  text "EXT_5V" at 38.4,68 h0.75
  text "EXT_3V" at -13.2,67.8 h0.75
  text "GND" at 39.2,65.4 h0.9
  text "GND" at -12.8,65.2 h0.9
  text "PB9" at 39.2,62.8 h0.9
  text "VDD" at -12.8,62.6 h0.9
  text "PC13" at -12.8,60.2 h0.9
  text "PB8" at 39.2,60.2 h0.9
  text "PC14" at -12.8,57.6 h0.9
  text "GND" at 39.2,57.6 h0.9
  text "BOOT0" at 38.6,55.2 h0.75
  text "PC15" at -12.8,55 h0.9
  text "PH0" at -12.8,52.6 h0.9
  text "PB7" at 39.2,52.6 h0.9
  text "PH1" at -12.8,50 h0.9
  text "PB6" at 39.2,50 h0.9
  text "Idd Measure" at 16,49.4 h1
  text "on" at 10.4,49.2 h1
  text "GND" at -12.8,47.6 h0.9
  text "PB5" at 39.2,47.4 h0.9
  text "NRST" at -12.8,45 h0.9
  text "PB4" at 39.2,45 h0.9
  text "off" at 16.2,44.2 h1
  text "PC0" at -12.8,42.4 h0.9
  text "PB3" at 39.2,42.4 h0.9
  text "PC1" at -12.8,40 h0.9
  text "PD2" at 39.2,39.8 h0.9
  text "PC2" at -12.8,37.4 h0.9
  text "MB963 B" at 24.4,37.4 h1.5
  text "112mm" at -28.042,37.347 h1.52 r90
  text "112mm" at 62.255,37.347 h1.52 r90
  text "PC12" at 39.2,37.2 h0.9
  text "PC3" at -12.8,34.8 h0.9
  text "PC11" at 39.2,34.8 h0.9
  text "PA0" at -12.8,32.4 h0.9
  text "PC10" at 39.2,32.2 h0.9
  text "PA1" at -12.8,29.8 h0.9
  text "PA15" at 39.2,29.6 h0.9
  text "68.58mm" at -16.993,28.805 h1.52 r90
  text "3V" at 31.6,28.8 h1.27
  text "68.58mm" at 45.999,28.804 h1.52 r90
  text "PA2" at -12.8,27.2 h0.9
  text "PA14" at 39.2,27.2 h0.9
  text "VDD" at 31,26.2 h1.27
  text "PA3" at -12.8,24.6 h0.9
  text "PA13" at 39.2,24.6 h0.9
  text "VBAT" at 31.2,23.6 h1.27
  text "PA4" at -12.8,22 h0.9
  text "PA12" at 39.2,22 h0.9
  text "PA11" at 39.2,19.6 h0.9
  text "PA5" at -12.8,19.4 h0.9
  text "PA10" at 39.2,17 h0.9
  text "PB2" at -12.819,16.936 h0.9
  text "PA9" at 39.2,14.6 h0.9
  text "PB10" at -12.819,14.536 h0.9
  text "PA8" at 39.2,12 h0.9
  text "PB11" at -12.819,11.936 h0.9
  text "PC9" at 39.2,9.4 h0.9
  text "PB12" at -12.819,9.336 h0.9
  text "PC8" at 39.2,7 h0.9
  text "PB13" at -12.798,6.912 h0.9
  text "PC7" at 39.2,4.4 h0.9
  text "PB14" at -12.841,4.363 h0.9
  text "PB7" at -6.2,2.2 h1
  text "PB6" at 32.8,2.2 h1
  text "PC6" at 39.223,1.863 h0.9
  text "PB15" at -12.804,1.75 h0.9
  text "SLIDER" at 12,0.8 h1
  text "RESET" at 20.2,0.4 h1.5
  text "USER" at 2.2,0.2 h1.5
  text "GND" at 39.2,-0.6 h0.9
  text "GND" at -12.8,-1 h0.9
  text "14.82mm" at -16.993,-12.768 h1.52 r90
  text "14.82mm" at 45.999,-12.767 h1.52 r90
  text "45.72mm" at 9.456,-18.694 h1.52
  text "5mm" at -12.984,-21.437 h1.52
  text "5mm" at 37.736,-21.437 h1.52
  text "55.72mm" at 9.456,-25.552 h1.52
Silkscreen Bottom:
  region: 2.9,18.8 6.8,18.8 6.8,15.8 2.899,15.805 2.978,15.201 3.184,14.272 3.47,13.364 3.835,12.484 4.274,11.64 4.786,10.837 5.365,10.081 6.009,9.379 6.71,8.736 7.466,8.157 8.269,7.645 9.113,7.206 9.993,6.841 10.901,6.555 11.83,6.349 12.774,6.225 13.725,6.183 14.087,6.199 14.092,6.196 14.874,6.23 15.82,6.354 16.753,6.561 17.663,6.848 18.545,7.214 19.392,7.655 20.198,8.168 20.955,8.749 21.659,9.394 22.304,10.098 22.886,10.856 23.399,11.661 23.84,12.508 24.205,13.39 24.492,14.301 24.699,15.233 24.706,15.29 24.7,15.3 23.8,15.3 23.8,19.4 24.605,19.399 24.433,20.175 24.149,21.077 23.787,21.951 23.35,22.79 22.842,23.588 22.266,24.338 21.627,25.036 20.929,25.675 20.179,26.251 19.381,26.759 18.542,27.196 17.668,27.558 16.766,27.842 15.842,28.047 14.905,28.17 13.96,28.211 13.808,28.205 13.799,28.206 12.96,28.169 11.993,28.041 11.04,27.83 10.109,27.537 9.207,27.163 8.341,26.713 7.518,26.188 6.744,25.594 6.024,24.935 5.365,24.215 4.771,23.441 4.246,22.617 3.795,21.752 3.422,20.85 3.128,19.919 2.917,18.966 2.894,18.792 2.9,18.8
  lines w0.2: 1.01,58.98 19.21,58.98 19.21,64.979 1.01,64.979 1.01,58.98 ; 19.5,71.513 22.738,71.513 22.738,82.181 19.5,82.181 19.5,71.513 ; 35.3,71.413 38.539,71.413 38.539,82.081 35.3,82.081 35.3,71.413
  text "DEFAULT" at 32.8,72.4 h1.5 r270
  text "RESERVED" at 23.6,71.8 h1.5 r270
  text "SN" at 18,61.2 h1
Drill Drawing:
  drawing of 430 lines, arcs and shapes, not listed
  text "3.200mm" at -36.398,99.657 h1.27
  text "22.860mm" at 39.347,78.678 h1.27
  text "25.400mm" at -31.84,77.408 h1.27
  text "25.400mm" at 55.16,77.408 h1.27
  text "6.350mm" at 41.992,69.948 h1.27
  text "6.350mm" at -22.108,66.447 h1.27
  text "112.000mm" at 47.474,39.847 h1.27
  text "0.808mm" at 19.772,10.035 h1.27
  text "1.400mm" at -28.137,1.657 h1.27
  text "1.854mm" at 19.728,1.656 h1.27
  text "1.490mm" at 35.521,0.858 h1.27
  text "1.032mm" at -23.964,0.764 h1.27
  text "1.032mm" at 35.289,0.783 h1.27
  text "1.016mm" at -2.944,0.746 h1.27
  text "10.000mm" at -27.707,-0.543 h1.27
  text "1.300mm" at -4.328,-5.452 h1.27
  text "2.500mm" at 41.044,-5.743 h1.27
  text "3.000mm" at 29.072,-6.252 h1.27
  text "0.160mm" at -5.489,-7.452 h1.27
  text "0.200mm" at 12.702,-8.443 h1.27
  text "13.209mm" at -23.464,-8.802 h1.27
  text "13.000mm" at -31.822,-9.453 h1.27
  text "13.400mm" at 58.549,-9.453 h1.27
  text "1.538mm" at 17.582,-10.096 h1.27
  text "1.500mm" at 39.063,-10.482 h1.27
  text "0.400mm" at 11.144,-13.143 h1.27
  text "1.500mm" at -5.828,-17.353 h1.27
  text "1.500mm" at 26.053,-18.152 h1.27
  text "13.800mm" at 9.772,-18.353 h1.27
  text "53.028mm" at 9.268,-18.814 h1.27
  text "52.903mm" at 9.269,-19.145 h1.27
  text "49.800mm" at 9.218,-21.752 h1.27
  text "5.000mm" at -27.166,-23.453 h1.27
  text "5.000mm" at 46.992,-23.852 h1.27
  text "55.720mm" at 9.22,-27.952 h1.27
  text "45.720mm" at 9.22,-33.252 h1.27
